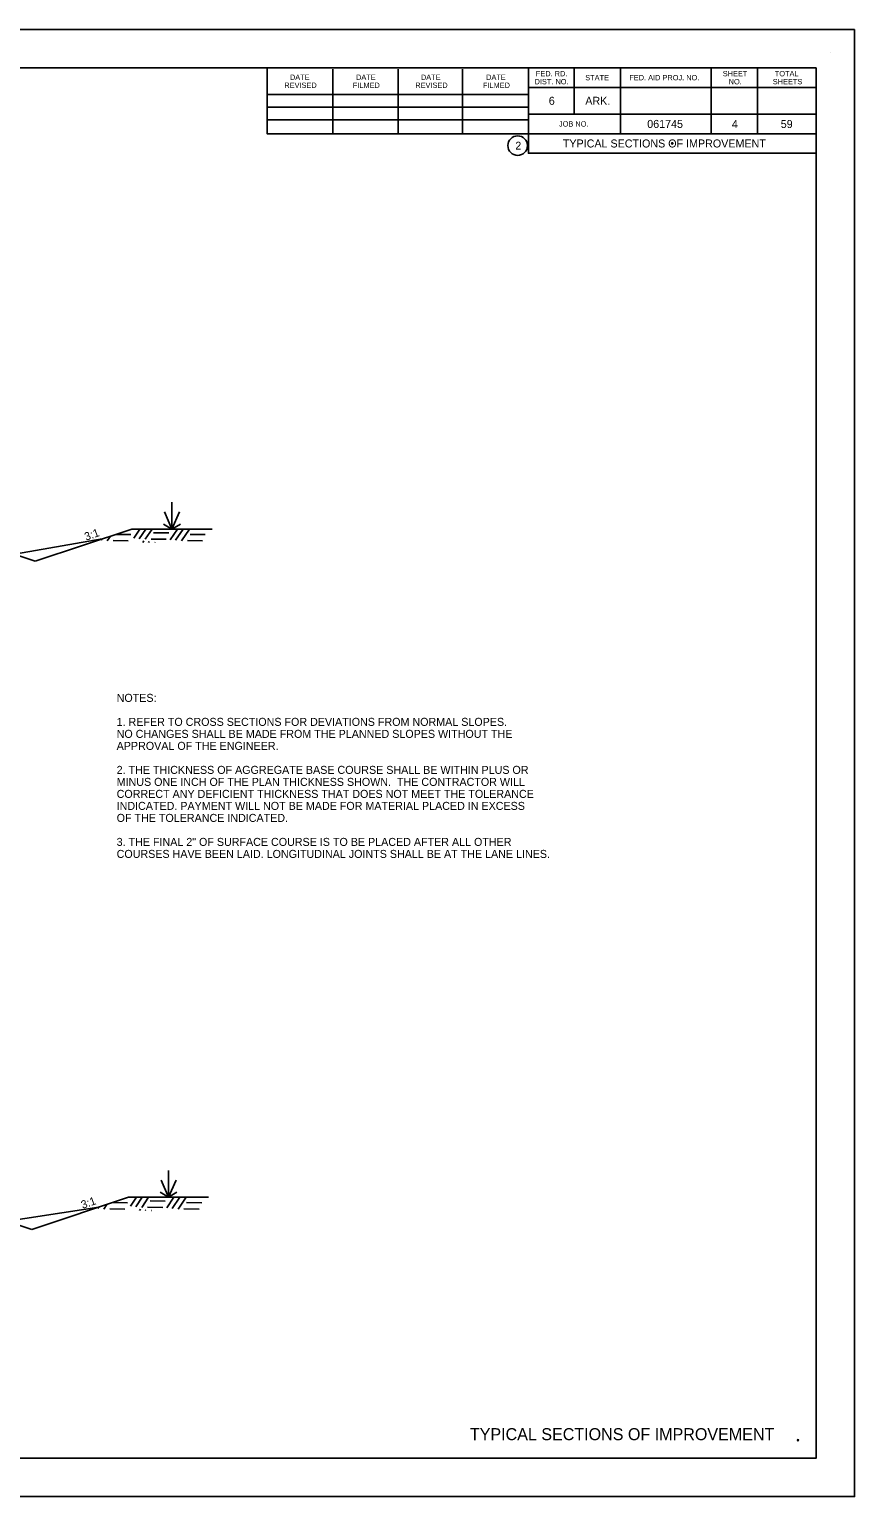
# Model space of a CAD drawing. Extents: x 2478 to 3210, y 439 to 841.
# Drawn here: x 2694.2 to 2817.8, y 438.6 to 658.6 of the extents above; entities that cross this region are included whole.
import ezdxf

# ---------------------------------------------------------------- set-up
doc = ezdxf.new("R2010")
doc.units = 0
for name, color, linetype in [('1', 7, 'Continuous'), ('60', 7, 'Continuous'), ('NO PLOT CELL', 7, 'Continuous'), ('R_Annotation', 7, 'Continuous'), ('R_Dimension', 7, 'Continuous'), ('R_Draft', 7, 'Continuous'), ('R_Exist Surface', 7, 'Continuous')]:
    doc.layers.add(name, color=color, linetype=linetype)

msp = doc.modelspace()

# ---------------------------------------------------------------- linework, layer by layer
at = {"layer": '1'}
for p, q in [((2814.23, 655.12), (2814.23, 655.12)), ((2492.97, 652.81), (2812.04, 652.81)), ((2729.78, 642.93), (2729.78, 652.81)), ((2739.64, 642.93), (2739.64, 652.61)), ((2749.4, 642.93), (2749.4, 652.61)), ((2759.08, 642.93), (2759.08, 652.61)), ((2768.94, 652.81), (2768.94, 640.01)), ((2775.78, 652.81), (2775.78, 645.87)), ((2782.72, 652.81), (2782.72, 642.93)), ((2796.3, 652.81), (2796.3, 642.93)), ((2803.24, 652.81), (2803.24, 642.93)), ((2812.04, 444.35), (2812.04, 652.81)), ((2812.04, 649.87), (2768.94, 649.87)), ((2812.04, 649.89), (2812.04, 649.89)), ((2729.78, 648.79), (2768.94, 648.79)), ((2729.78, 646.93), (2768.94, 646.93)), ((2729.78, 644.99), (2768.94, 644.99)), ((2729.78, 642.93), (2729.78, 644.99)), ((2812.04, 645.87), (2768.94, 645.87)), ((2771.9, 645.87), (2812.04, 645.87)), ((2812.04, 642.93), (2729.78, 642.93)), ((2768.94, 640.01), (2812.04, 640.01)), ((2812.04, 444.35), (2492.97, 444.35))]:
    msp.add_line(p, q, dxfattribs=at)
for points in [[(2817.81, 658.58), (2477.81, 658.58), (2477.81, 438.58), (2817.81, 438.58)], [(2492.97, 444.35), (2492.97, 652.81), (2729.78, 652.81), (2729.78, 642.93), (2768.94, 642.93), (2768.94, 640.01), (2812.04, 640.01), (2812.04, 444.35)]]:
    msp.add_lwpolyline(points, close=True, dxfattribs=at)
msp.add_circle((2767.33, 641.15), 1.47, dxfattribs=at)
at = {"layer": 'NO PLOT CELL'}
for centre in [(2790.49, 641.47), (2809.34, 447.05)]:
    msp.add_circle(centre, 0.1, dxfattribs=at)
at = {"layer": 'R_Annotation'}
for p, q in [((2677.54, 584.65), (2695.04, 578.82)), ((2695.04, 578.82), (2709.54, 583.65)), ((2709.54, 583.65), (2721.54, 583.65)), ((2677.03, 484.47), (2694.53, 478.63)), ((2694.53, 478.63), (2709.03, 483.47)), ((2709.03, 483.47), (2721.03, 483.47))]:
    msp.add_line(p, q, dxfattribs=at)
at = {"layer": 'R_Dimension'}
for p, q in [((2709.82, 582.3), (2710.74, 583.65)), ((2710.62, 582.21), (2711.6, 583.65)), ((2711.51, 582.12), (2712.55, 583.65)), ((2712.79, 583.1), (2715.05, 583.08)), ((2715.28, 582.06), (2716.35, 583.65)), ((2716.07, 581.97), (2717.21, 583.65)), ((2716.96, 581.88), (2718.16, 583.65)), ((2704.95, 581.97), (2705.08, 582.17)), ((2705.84, 581.88), (2706.31, 582.58)), ((2706.73, 581.92), (2708.99, 581.9)), ((2707.16, 582.86), (2709.38, 582.84)), ((2711.18, 581.65), (2711.33, 581.88)), ((2712.04, 581.65), (2712.12, 581.79)), ((2712.4, 582.16), (2714.66, 582.14)), ((2712.99, 581.65), (2713.01, 581.69)), ((2717.85, 581.92), (2720.11, 581.9)), ((2718.24, 582.86), (2720.5, 582.84)), ((2704.44, 481.78), (2704.57, 481.98)), ((2705.33, 481.69), (2705.8, 482.39)), ((2706.65, 482.67), (2708.87, 482.66)), ((2709.32, 482.12), (2710.23, 483.47)), ((2710.11, 482.02), (2711.09, 483.47)), ((2711, 481.93), (2712.04, 483.47)), ((2711.89, 481.97), (2714.16, 481.95)), ((2712.28, 482.92), (2714.54, 482.9)), ((2714.77, 481.88), (2715.84, 483.47)), ((2715.56, 481.78), (2716.7, 483.47)), ((2716.45, 481.69), (2717.65, 483.47)), ((2717.73, 482.67), (2720, 482.66)), ((2706.22, 481.73), (2708.48, 481.71)), ((2710.67, 481.47), (2710.82, 481.69)), ((2711.53, 481.47), (2711.62, 481.6)), ((2712.48, 481.47), (2712.51, 481.51)), ((2717.34, 481.73), (2719.61, 481.71))]:
    msp.add_line(p, q, dxfattribs=at)
at = {"layer": 'R_Draft'}
for p, q in [((2715.54, 583.65), (2715.54, 587.67)), ((2715.54, 583.65), (2714.4, 586.24)), ((2715.54, 583.65), (2716.68, 586.24)), ((2715.54, 583.65), (2714.28, 584.41)), ((2715.54, 583.65), (2716.8, 584.41)), ((2715.03, 483.47), (2715.03, 487.49)), ((2715.03, 483.47), (2713.78, 484.23)), ((2715.03, 483.47), (2713.9, 486.05)), ((2715.03, 483.47), (2716.17, 486.05)), ((2715.03, 483.47), (2716.29, 484.23))]:
    msp.add_line(p, q, dxfattribs=at)
at = {"layer": 'R_Exist Surface'}
for points in [[(2559.05, 580.01), (2580.8, 583.04), (2610.27, 580.01), (2642.75, 581.69), (2680.21, 577.82), (2705.08, 582.17)], [(2567.84, 481.29), (2572.78, 480.92), (2588.81, 481.64), (2601.63, 478.38), (2624.24, 475.51), (2653.36, 474.14), (2704.57, 481.98)]]:
    msp.add_lwpolyline(points, dxfattribs=at)

# ---------------------------------------------------------------- texts
at = {"layer": '1'}
for s, height, p in [('DATE', 0.8, (2733.21, 651)), ('DATE', 0.8, (2743.11, 651)), ('DATE', 0.8, (2752.83, 651)), ('DATE', 0.8, (2762.6, 651)), ('FED. RD.', 0.8, (2770.05, 651.54)), ('STATE', 0.8, (2777.45, 650.94)), ('FED. AID PROJ. NO.', 0.8, (2784.05, 650.94)), ('SHEET', 0.8, (2798.05, 651.54)), ('TOTAL', 0.8, (2805.85, 651.54)), ('REVISED', 0.8, (2732.37, 649.8)), ('FILMED', 0.8, (2742.63, 649.8)), ('REVISED', 0.8, (2751.99, 649.8)), ('FILMED', 0.8, (2762.12, 649.8)), ('DIST. NO.', 0.8, (2769.86, 650.34)), ('NO.', 0.8, (2798.94, 650.34)), ('SHEETS', 0.8, (2805.55, 650.34)), ('6', 1.2, (2771.99, 647.27)), ('ARK.', 1.2, (2777.46, 647.27)), ('JOB NO.', 0.8, (2773.52, 644)), ('061745', 1.2, (2786.74, 643.8)), ('4', 1.2, (2799.42, 643.79)), ('59', 1.2, (2806.74, 643.79)), ('2', 1.17, (2766.99, 640.56)), ('TYPICAL SECTIONS OF IMPROVEMENT', 1.2, (2774.1, 640.87))]:
    msp.add_text(s, height=height, dxfattribs=at).set_placement(p)
at = {"layer": '60'}
msp.add_text('TYPICAL SECTIONS OF IMPROVEMENT', height=1.8, dxfattribs=at).set_placement((2760.17, 447.05))
at = {"layer": 'R_Annotation'}
for p in [(2702.67, 581.9), (2702.16, 481.72)]:
    msp.add_text('3:1', height=1.2, rotation=19.3394, dxfattribs=at).set_placement(p)
for s, p in [('NOTES:', (2707.25, 557.75)), ('1. REFER TO CROSS SECTIONS FOR DEVIATIONS FROM NORMAL SLOPES. ', (2707.25, 554.15)), ('NO CHANGES SHALL BE MADE FROM THE PLANNED SLOPES WITHOUT THE', (2707.25, 552.35)), ('APPROVAL OF THE ENGINEER.', (2707.25, 550.55)), ('2. THE THICKNESS OF AGGREGATE BASE COURSE SHALL BE WITHIN PLUS OR', (2707.25, 546.95)), ('MINUS ONE INCH OF THE PLAN THICKNESS SHOWN.  THE CONTRACTOR WILL', (2707.25, 545.15)), ('CORRECT ANY DEFICIENT THICKNESS THAT DOES NOT MEET THE TOLERANCE', (2707.25, 543.35)), ('INDICATED. PAYMENT WILL NOT BE MADE FOR MATERIAL PLACED IN EXCESS', (2707.25, 541.55)), ('OF THE TOLERANCE INDICATED.', (2707.25, 539.75)), ('3. THE FINAL 2" OF SURFACE COURSE IS TO BE PLACED AFTER ALL OTHER', (2707.25, 536.15)), ('COURSES HAVE BEEN LAID. LONGITUDINAL JOINTS SHALL BE AT THE LANE LINES.', (2707.25, 534.35))]:
    msp.add_text(s, height=1.2, dxfattribs=at).set_placement(p)

doc.saveas('drawing.dxf')
